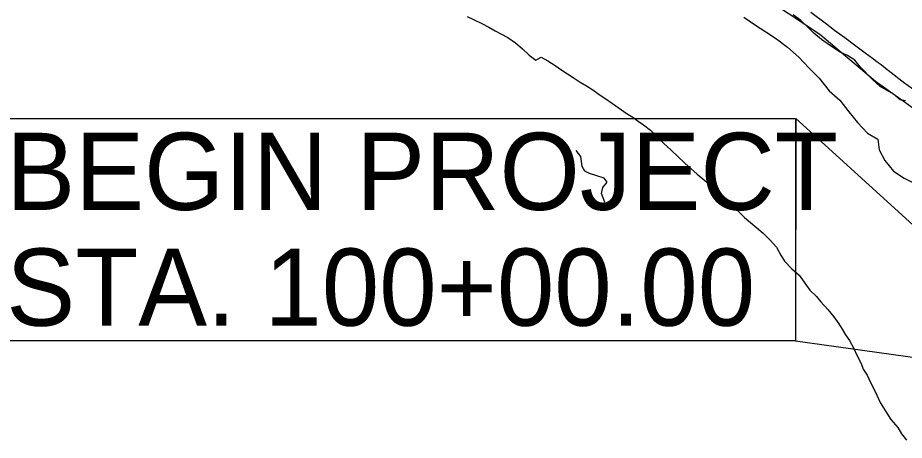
# Model space of a CAD drawing. Extents: x 0 to 34, y 0 to 22.
# Drawn here: x 3.024 to 4.632, y 17.542 to 18.308 of the extents above; entities that cross this region are included whole.
import ezdxf

# ---------------------------------------------------------------- set-up
doc = ezdxf.new("R2010")
doc.units = 0
for name, color, linetype in [('Default', 7, 'Continuous'), ('GM_X_Major_River', 7, 'Continuous'), ('GM_X_Minor_River', 7, 'Continuous'), ('GM_X_Rail_Line', 7, 'Continuous'), ('GM_X_US_Route', 7, 'Continuous'), ('SH_Cut_Line', 7, 'Continuous'), ('SH_Text', 7, 'Continuous')]:
    doc.layers.add(name, color=color, linetype=linetype)

msp = doc.modelspace()

# ---------------------------------------------------------------- linework, layer by layer
at = {"layer": 'Default'}
msp.add_lwpolyline([(4.3411, 18.3094), (4.3604, 18.2961), (4.3805, 18.2825), (4.3998, 18.2703), (4.4203, 18.2548), (4.4404, 18.2369), (4.4586, 18.2175), (4.4772, 18.1985), (4.4954, 18.1758), (4.5151, 18.1587), (4.5314, 18.1378), (4.5473, 18.118), (4.5651, 18.099), (4.5841, 18.088), (4.5864, 18.069), (4.5966, 18.0493), (4.6125, 18.0303), (4.6315, 18.0174), (4.6508, 18.0075)], dxfattribs=at)
at = {"layer": 'GM_X_Major_River'}
for points in [[(3.8392, 18.3105), (3.8505, 18.3054), (3.8655, 18.298), (3.8783, 18.2914), (3.8896, 18.2848), (3.8998, 18.2793), (3.9126, 18.2723), (3.9265, 18.263), (3.9396, 18.2519), (3.9516, 18.2407), (3.9636, 18.2314), (3.9731, 18.237), (3.9852, 18.2304), (3.9983, 18.2218), (4.0107, 18.2133), (4.0212, 18.2064), (4.0314, 18.2002), (4.0442, 18.1916), (4.0555, 18.1846), (4.0667, 18.1773), (4.0787, 18.1688), (4.0885, 18.1622), (4.1024, 18.1529), (4.1295, 18.1343), (4.1392, 18.1277), (4.149, 18.1208), (4.1591, 18.1138), (4.1715, 18.1045), (4.185, 18.0907), (4.1951, 18.0811), (4.2089, 18.0684), (4.2205, 18.0572), (4.2344, 18.0437), (4.2445, 18.0349), (4.2561, 18.0245), (4.27, 18.0129), (4.282, 18.0029), (4.2959, 17.9917), (4.3079, 17.9805), (4.3206, 17.9675), (4.3322, 17.9559), (4.3419, 17.9459), (4.3528, 17.9371), (4.376, 17.9178), (4.3887, 17.9051), (4.4003, 17.892), (4.4081, 17.8779), (4.4148, 17.8668), (4.4278, 17.853), (4.441, 17.8414), (4.4605, 17.814)], [(4.6339, 18.1574), (4.6241, 18.1594), (4.6121, 18.1698), (4.588, 18.1838), (4.5742, 18.1961), (4.5517, 18.2192), (4.542, 18.2315), (4.5289, 18.24), (4.5153, 18.2459), (4.5018, 18.2552), (4.492, 18.2618), (4.4819, 18.2691), (4.4676, 18.2803), (4.4557, 18.2922), (4.4444, 18.303), (4.4305, 18.3134)], [(4.4605, 17.814), (4.4725, 17.8028), (4.4803, 17.7933), (4.4931, 17.7794), (4.5039, 17.7657), (4.5132, 17.7534), (4.5192, 17.7435), (4.5255, 17.7331), (4.5326, 17.7228), (4.5404, 17.7087), (4.546, 17.6961), (4.5534, 17.6812), (4.5575, 17.6709), (4.5645, 17.6598), (4.5708, 17.6468), (4.5775, 17.6342), (4.582, 17.6239), (4.5883, 17.6105), (4.5942, 17.601), (4.6005, 17.591), (4.6076, 17.5799), (4.62, 17.5653), (4.6271, 17.5539), (4.636, 17.542)]]:
    msp.add_lwpolyline(points, dxfattribs=at)
at = {"layer": 'GM_X_Minor_River'}
msp.add_lwpolyline([(4.0885, 17.9736), (4.0826, 17.9896), (4.0852, 18.0002), (4.0932, 18.0101), (4.0872, 18.0173), (4.061, 18.0257), (4.0523, 18.03), (4.0474, 18.0383), (4.0452, 18.0569), (4.0365, 18.0676)], dxfattribs=at)
at = {"layer": 'GM_X_Rail_Line'}
msp.add_lwpolyline([(4.6895, 18.1137), (4.6296, 18.1567), (4.5798, 18.1927), (4.4784, 18.2777), (4.364, 18.3544), (4.2732, 18.4099), (4.1565, 18.4748), (4.0563, 18.5278), (3.9136, 18.6104), (3.633, 18.7426), (3.5445, 18.7756), (3.2856, 18.8723), (3.0993, 18.936), (3.041, 18.9562), (2.9951, 18.9667), (2.9337, 18.9715), (2.8642, 18.9726), (2.7699, 18.9856), (2.7152, 18.9964), (2.6303, 19.0094), (2.3595, 19.0564), (2.3142, 19.0671)], dxfattribs=at)
at = {"layer": 'GM_X_US_Route'}
for points in [[(4.4622, 18.3183), (4.4907, 18.2972), (4.4966, 18.2927), (4.5055, 18.2859), (4.5135, 18.28), (4.5241, 18.2723), (4.5414, 18.2592), (4.5609, 18.2447), (4.5743, 18.2348), (4.5847, 18.2269), (4.5897, 18.2232), (4.6011, 18.2146), (4.6027, 18.2134)], [(4.6027, 18.2134), (4.633, 18.1898), (4.6365, 18.1873), (4.6415, 18.1836), (4.645, 18.181), (4.6594, 18.1702), (4.6683, 18.1634), (4.6889, 18.1484), (4.6967, 18.1423), (4.7115, 18.1309), (4.7288, 18.1169), (4.7385, 18.1083), (4.7454, 18.1012), (4.7516, 18.0944), (4.7583, 18.0865)]]:
    msp.add_lwpolyline(points, dxfattribs=at)
at = {"layer": 'SH_Cut_Line'}
msp.add_lwpolyline([(4.3411, 18.3094), (4.3604, 18.2961), (4.3805, 18.2825), (4.3998, 18.2703), (4.4203, 18.2548), (4.4404, 18.2369), (4.4586, 18.2175), (4.4772, 18.1985), (4.4954, 18.1758), (4.5151, 18.1587), (4.5314, 18.1378), (4.5473, 18.118), (4.5651, 18.099), (4.5841, 18.088), (4.5864, 18.069), (4.5966, 18.0493), (4.6125, 18.0303), (4.6315, 18.0174), (4.6508, 18.0075)], dxfattribs=at)
at = {"layer": 'SH_Text'}
for points in [[(2.9993, 18.1253), (4.4348, 18.1253), (4.4348, 17.7221), (2.9993, 17.7221)], [(4.4348, 17.7221), (4.9594, 17.6492), (4.4349, 18.1254)]]:
    msp.add_lwpolyline(points, close=True, dxfattribs=at)

# ---------------------------------------------------------------- texts
for s, p in [('BEGIN PROJECT', (3.0031, 17.9597)), ('STA. 100+00.00', (3.0031, 17.7497))]:
    msp.add_text(s, height=0.14, dxfattribs=at).set_placement(p)

doc.saveas('drawing.dxf')
